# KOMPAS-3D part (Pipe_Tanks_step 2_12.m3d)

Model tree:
1. X Axis
2. Y Axis
3. Z Axis  (labels: T-Bend Dn 50; Pipe Dn 50)
     Òîëùèíà ñòåíêè 1 = 1

Referenced files in C:\Documents and Settings\kashirsky\Мои документы\Camtasia Studio\Pipelines3D\Tanks\: Tanks_step 2.a3d
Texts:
  Pipe Dn 50
  Steel ASTM A295
  Three Point Plane
  Plane at Angle
  Line and Point Plane
  Axis through Two Vertices
  Axis of Feature
  Axis of Conical Surface
  Axis through Edge
  Trim by Surface
  Trim by Sketch
  Feature with No History
  Intersection Axis of Two Planes
  Two Line Plane
  Line and Face Plane
  Bend by line
  Hole in sheet body
  Cut in sheet body
  Point in CM
  Linear Dimension from Line to Point
  Surface Finish Symbol
  Geometric Tolerance Symbol
  Leader #1
  Leader #2
  Leader #3
  Shape Deviations and Datum
  Node point number
  Mark of coordination axis
  Node point designation
  Mark/Reference designation with leader
  Mark/reference designation on line
  Mark/Reference designation without leader
  T-Bend Dn 50
  Plane of section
